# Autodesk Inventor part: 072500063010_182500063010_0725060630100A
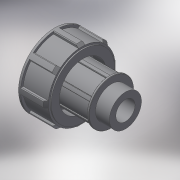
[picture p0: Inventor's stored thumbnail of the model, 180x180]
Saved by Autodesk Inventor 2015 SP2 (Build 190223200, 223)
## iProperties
Created: 2017-04
Part Number: 072500063010_182500063010_0725060630100A
Material: Generic
Description: PLASSON THREADED ADAPTOR 63-1"
Document SubType Name: Modeling
Designer: KIM
Density: 1 g/cm^3
Appearance: Default
Author: KIM
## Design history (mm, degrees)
derived "07250.ipt"
feature "Solid1::07250.ipt"
tag "TaggingFeature1"
body "Solid1"
other parameters: "d1" = 33.249, "d2" = 108, "d6" = 113, "d7" = 105.09, "d8" = 90.4, "d9" = 63, "d10" = 69.8229, "d12" = 19.9494, "d13" = 26.5992, "d14" = 23, "d15" = 84.75, "d16" = 3.24, "d17" = 43.2, "d19" = 24, "d24" = 6.6498, "d25" = 3.3249, "d27" = 0, "d28" = 2.65992, "d31" = 0.66498, "d35" = 360 deg, "d41" = 29.337, "d56" = 68.04, "d57" = 6.3, "d58" = 3.15, "d60" = 0, "d61" = 0.33249, "d64" = 0.33249, "d68" = 360 deg, "d_" = 63, "R_" = 33.249, "E_" = 113, "H_" = 108, "d55" = 63
